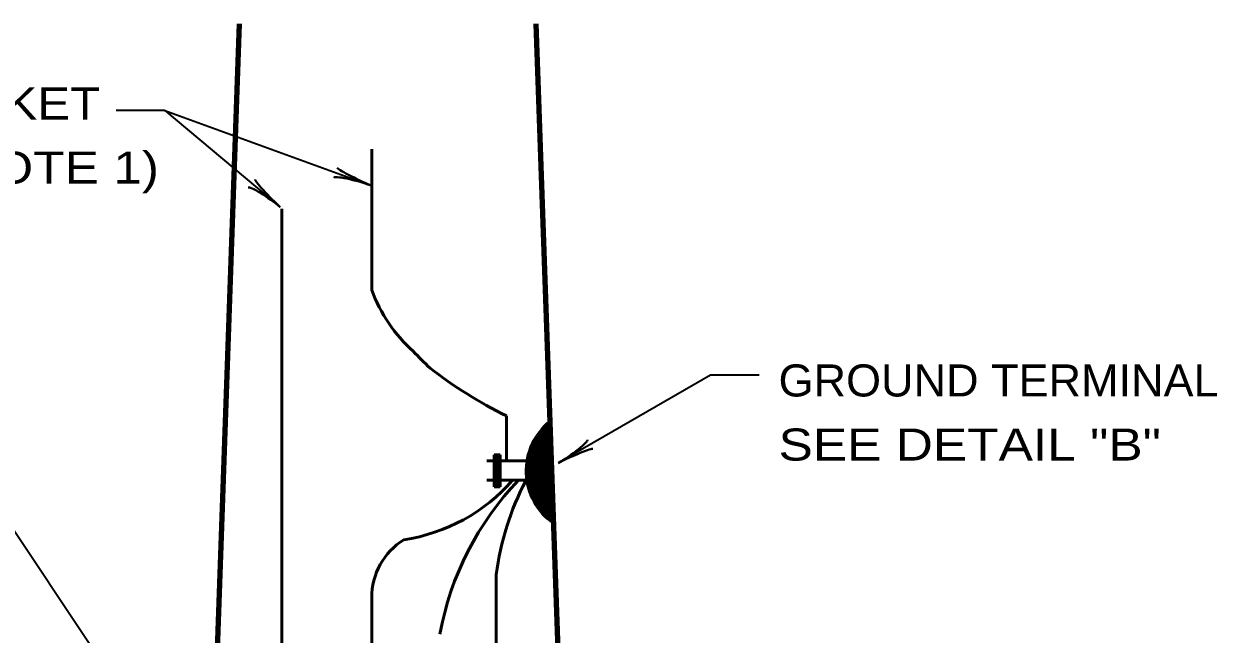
# Model space of a CAD drawing. Extents: x -153 to 527, y -247 to 194.
# Drawn here: x -71.2 to 21.9, y -113 to -65.4 of the extents above; entities that cross this region are included whole.
import ezdxf

# ---------------------------------------------------------------- set-up
doc = ezdxf.new("R2010")
doc.units = 0
doc.layers.add('1', color=7, linetype='Continuous', lineweight=53)

msp = doc.modelspace()

# ---------------------------------------------------------------- linework, layer by layer
at = {"layer": '1', "lineweight": 90}
for p, q in [((-57.166, -146.336), (-54.34, -65.386)), ((-28.359, -146.336), (-31.185, -65.386))]:
    msp.add_line(p, q, dxfattribs=at)
at = {"layer": '1', "lineweight": 35}
for p, q in [((-60.145, -72.137), (-63.943, -72.137)), ((-60.145, -72.137), (-51.165, -79.673)), ((-60.145, -72.137), (-44.137, -77.964)), ((-73.402, -102.672), (-53.158, -133))]:
    msp.add_line(p, q, dxfattribs=at)
at = {"layer": '1'}
for p, q in [((-44.016, -75.148), (-44.016, -86.148)), ((-51.044, -131.56), (-51.044, -79.806)), ((-33.51, -99.462), (-33.51, -95.962)), ((-31.912, -99.478), (-35.035, -99.478)), ((-34.476, -99.005), (-34.476, -101.505)), ((-34.476, -99.005), (-34.005, -99.005)), ((-34.476, -99.066), (-34.005, -99.066)), ((-34.476, -99.123), (-34.005, -99.123)), ((-34.476, -99.194), (-34.005, -99.194)), ((-34.476, -99.208), (-34.005, -99.208)), ((-34.476, -99.222), (-34.005, -99.222)), ((-34.476, -99.293), (-34.005, -99.293)), ((-34.476, -99.364), (-34.005, -99.364)), ((-34.476, -99.435), (-34.005, -99.435)), ((-34.476, -99.534), (-34.005, -99.534)), ((-34.476, -99.562), (-34.005, -99.562)), ((-34.005, -99.005), (-34.005, -101.505)), ((-34.476, -99.59), (-34.005, -99.59)), ((-34.476, -99.647), (-34.005, -99.647)), ((-34.476, -99.647), (-34.005, -99.647)), ((-34.476, -99.689), (-34.005, -99.689)), ((-34.476, -99.718), (-34.005, -99.718)), ((-34.476, -99.732), (-34.005, -99.732)), ((-34.476, -99.746), (-34.005, -99.746)), ((-34.476, -99.76), (-34.005, -99.76)), ((-34.476, -99.774), (-34.005, -99.774)), ((-34.476, -99.774), (-34.005, -99.774)), ((-34.476, -99.817), (-34.005, -99.817)), ((-34.476, -99.859), (-34.005, -99.859)), ((-34.476, -99.888), (-34.005, -99.888)), ((-34.476, -99.888), (-34.005, -99.888)), ((-34.476, -99.888), (-34.005, -99.888)), ((-34.476, -99.944), (-34.005, -99.944)), ((-34.476, -99.987), (-34.005, -99.987)), ((-34.476, -100.029), (-34.005, -100.029)), ((-34.476, -100.072), (-34.005, -100.072)), ((-34.476, -100.072), (-34.005, -100.072)), ((-34.476, -100.1), (-34.005, -100.1)), ((-34.476, -100.143), (-34.005, -100.143)), ((-34.476, -100.185), (-34.005, -100.185)), ((-34.476, -100.213), (-34.005, -100.213)), ((-34.476, -100.27), (-34.005, -100.27)), ((-34.476, -100.284), (-34.005, -100.284)), ((-34.476, -100.327), (-34.005, -100.327)), ((-34.476, -100.341), (-34.005, -100.341)), ((-34.476, -100.369), (-34.005, -100.369)), ((-34.476, -100.426), (-34.005, -100.426)), ((-34.476, -100.468), (-34.005, -100.468)), ((-31.922, -100.978), (-35.035, -100.978)), ((-34.476, -100.525), (-34.005, -100.525)), ((-34.476, -100.567), (-34.005, -100.567)), ((-34.476, -100.61), (-34.005, -100.61)), ((-34.476, -100.624), (-34.005, -100.624)), ((-34.476, -100.652), (-34.005, -100.652)), ((-34.476, -100.695), (-34.005, -100.695)), ((-34.476, -100.737), (-34.005, -100.737)), ((-34.476, -100.78), (-34.005, -100.78)), ((-34.476, -100.837), (-34.005, -100.837)), ((-34.476, -100.851), (-34.005, -100.851)), ((-34.476, -100.907), (-34.005, -100.907)), ((-34.476, -100.936), (-34.005, -100.936)), ((-34.476, -100.95), (-34.005, -100.95)), ((-34.476, -100.992), (-34.005, -100.992)), ((-34.476, -101.007), (-34.005, -101.007)), ((-34.476, -101.021), (-34.005, -101.021)), ((-34.476, -101.091), (-34.005, -101.091)), ((-34.476, -101.106), (-34.005, -101.106)), ((-34.476, -101.12), (-34.005, -101.12)), ((-34.476, -101.134), (-34.005, -101.134)), ((-34.476, -101.191), (-34.005, -101.191)), ((-34.476, -101.191), (-34.005, -101.191)), ((-34.476, -101.191), (-34.005, -101.191)), ((-34.476, -101.205), (-34.005, -101.205)), ((-34.476, -101.205), (-34.005, -101.205)), ((-34.476, -101.205), (-34.005, -101.205)), ((-34.476, -101.219), (-34.005, -101.219)), ((-34.476, -101.219), (-34.005, -101.219)), ((-34.476, -101.247), (-34.005, -101.247)), ((-34.476, -101.29), (-34.005, -101.29)), ((-34.476, -101.318), (-34.005, -101.318)), ((-34.476, -101.332), (-34.005, -101.332)), ((-34.476, -101.375), (-34.005, -101.375)), ((-34.476, -101.403), (-34.005, -101.403)), ((-34.476, -101.431), (-34.005, -101.431)), ((-34.476, -101.488), (-34.005, -101.488)), ((-34.005, -101.505), (-34.476, -101.505)), ((-44.016, -131.56), (-44.016, -110.148))]:
    msp.add_line(p, q, dxfattribs=at)
at = {"layer": '1', "lineweight": 35}
msp.add_lwpolyline([(-13.812, -92.796), (-17.61, -92.796), (-29.457, -99.636)], dxfattribs=at)
at = {"layer": '1'}
for points in [[(-30.247, -96.54), (-29.939, -104.143), (-29.98, -104.143), (-30.329, -96.663), (-30.432, -96.725), (-30.062, -104.102), (-30.514, -96.766), (-30.144, -104.041), (-30.596, -96.951), (-30.226, -103.959), (-30.72, -97.033), (-30.329, -103.876), (-30.679, -97.054), (-30.432, -103.753), (-30.822, -97.156), (-30.535, -103.712), (-30.843, -97.218), (-30.637, -103.568), (-29.877, -104.226), (-30.761, -103.465), (-30.966, -97.3), (-30.309, -96.663), (-30.925, -97.403), (-30.74, -103.301), (-30.863, -103.239), (-31.048, -97.506), (-30.863, -103.301), (-31.131, -97.608), (-30.946, -103.198), (-30.658, -103.465), (-30.699, -103.321), (-31.007, -103.054), (-31.213, -97.732), (-31.007, -103.034), (-31.028, -103.095), (-31.316, -97.896), (-31.131, -102.951), (-31.418, -98.019), (-31.213, -102.767), (-31.48, -98.266)], [(-31.48, -98.266), (-31.316, -102.602), (-31.583, -98.451), (-31.418, -102.397), (-31.706, -98.718), (-31.521, -102.171), (-31.768, -99.088), (-31.603, -101.842), (-31.829, -99.376), (-31.685, -101.698), (-31.912, -99.746), (-31.788, -101.307), (-31.665, -98.759), (-31.644, -99.499), (-31.912, -100.465), (-31.644, -101.821), (-31.274, -102.52), (-31.09, -102.951), (-30.966, -103.178)], [(-34.308, -108.335), (-34.308, -158.336), (5.692, -158.336), (5.692, -161.336)]]:
    msp.add_lwpolyline(points, dxfattribs=at)
for centre, radius, start, end in [((-32.73, -81.993), 12.027, 200.21181, 227.97829), ((-19.81, -71.187), 28.8, 223.2685, 226.947), ((-18.458, -65.283), 34.173, 232.05658, 243.86759), ((-26.986, -100.261), 4.988, 128.68208, 235.31633), ((-43.572, -91.785), 13.988, 278.41314, 318.91418), ((-15.721, -117.135), 23.347, 136.20957, 169.7656), ((-12.921, -111.057), 21.559, 152.29728, 172.74751), ((-38.728, -110.11), 5.287, 121.93375, 180.41081)]:
    msp.add_arc(centre, radius, start, end, dxfattribs=at)
at = {"layer": '1', "lineweight": 40}
for centre, major_axis, ratio, start_param, end_param in [((-45.117, -77.382), (1.59, -0.766), 0.07063, 3.140715, 5.41811), ((-45.117, -77.382), (1.59, -0.766), 0.07063, 3.140715, 5.41811), ((-52.179, -79.183), (1.468, -1.028), 0.122415, 0.896353, 3.141593), ((-51.887, -78.79), (-1.233, 1.264), 0.07063, 6.282307, 8.559703), ((-45.257, -77.85), (1.731, -0.464), 0.122415, 0.896353, 3.141593), ((-45.257, -77.85), (1.731, -0.464), 0.122415, 0.896353, 3.141593), ((-28.651, -98.851), (-1.468, -1.028), 0.122415, 0.896353, 3.141593), ((-28.381, -99.259), (1.609, 0.726), 0.07063, 6.282307, 8.559703)]:
    msp.add_ellipse(centre, major_axis=major_axis, ratio=ratio, start_param=start_param, end_param=end_param, dxfattribs=at)

# ---------------------------------------------------------------- texts
at = {"layer": '1'}
for s, width, p in [('POLE AND BRACKET', 1.15, (-103.862, -72.848)), ('CABLES (SEE NOTE 1)', 1.2, (-103.862, -77.848)), ('GROUND TERMINAL', 1.05, (-12.293, -94.449)), ('SEE DETAIL "B"', 1.2, (-12.293, -99.449))]:
    msp.add_text(s, height=2.5, dxfattribs=dict(at, width=width)).set_placement(p)

doc.saveas('drawing.dxf')
